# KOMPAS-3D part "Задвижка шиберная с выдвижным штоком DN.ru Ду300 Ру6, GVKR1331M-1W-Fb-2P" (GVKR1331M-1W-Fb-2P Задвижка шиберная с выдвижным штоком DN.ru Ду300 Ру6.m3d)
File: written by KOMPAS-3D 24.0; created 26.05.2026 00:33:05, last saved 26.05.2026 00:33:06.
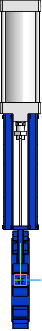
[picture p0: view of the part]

Document properties: Автор: R2D2; Полное имя файла: E:\Работа\Зайцев\GVKR1331M-1W-Fb-2P Задвижка шиберная с выдвижным штоком DN.ru Ду50-300 Ру16-10-6 с пневмоприводом\исходные материалы\DN300\DN300\GVKR1331M-1W-Fb-2P Задвижка шиберная с выдвижным штоком DN.ru Ду300 Ру6.m3d

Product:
- Part/product: Задвижка шиберная с выдвижным штоком DN.ru Ду300 Ру6  | designation GVKR1331M-1W-Fb-2P
    Масса: 70
    Раздел спецификации: Прочие изделия
    Примечание: D040-08799

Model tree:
1. Операция без истории:1

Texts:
  GVKR1331M-1W-Fb-2P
